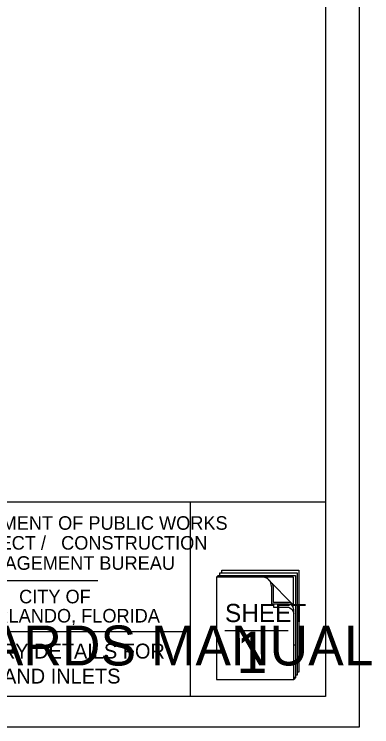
# Model space of a CAD drawing. Extents: x -7.1 to 10, y -5 to 6.
# Drawn here: x 7.28 to 10.04, y -5.04 to 0.46 of the extents above; entities that cross this region are included whole.
import ezdxf

# ---------------------------------------------------------------- set-up
doc = ezdxf.new("R2010")
doc.units = 0
doc.layers.add('Level 60', color=7, linetype='Continuous')
doc.layers.add('Level 62', color=7, linetype='Continuous')

msp = doc.modelspace()

# ---------------------------------------------------------------- linework, layer by layer
at = {"layer": 'Level 60'}
for p, q in [((9.2417, -3.9022), (9.4331, -4.0993)), ((7.9265, -3.9133), (7.1593, -3.9133)), ((9.416, -4.0867), (9.4347, -4.1006))]:
    msp.add_line(p, q, dxfattribs=at)
for points in [[(-7.0652, -5.0406), (9.9453, -5.0406), (9.9453, 5.9662), (-7.0652, 5.9662)], [(-6.384, 5.7493), (9.684, 5.7493), (9.684, -4.8063), (-6.384, -4.8063)], [(9.4356, -3.8861), (9.2545, -3.8861), (9.2077, -3.8863), (8.842, -3.8863), (8.8555, -3.8714), (9.4514, -3.8714), (9.4514, -4.6604), (9.4379, -4.6753), (9.4379, -4.1896), (9.4379, -4.1339), (9.4343, -4.1142), (9.4356, -4.0728)], [(8.842, -4.6753), (9.4379, -4.6753), (9.4379, -4.1896), (9.4379, -4.1589), (9.4379, -4.1339), (9.4379, -4.1339), (9.4343, -4.1142), (9.4227, -4.1021), (9.3973, -4.0928), (9.2703, -4.0928), (9.2703, -3.9645), (9.258, -3.919), (9.2361, -3.8965), (9.2077, -3.8863), (8.842, -3.8863)], [(9.2825, -4.0934), (9.2825, -4.1159), (9.3866, -4.1159), (9.3989, -4.1179), (9.4091, -4.122), (9.4189, -4.1288), (9.4269, -4.1368), (9.4314, -4.1454), (9.4379, -4.1658), (9.4377, -4.1327), (9.4343, -4.1142), (9.4227, -4.1021), (9.3973, -4.0928)]]:
    msp.add_lwpolyline(points, close=True, dxfattribs=at)
for points in [[(9.6844, -3.3069), (5.6643, -3.3069)], [(8.6415, -4.8065), (8.6415, -3.3069)], [(8.8826, -3.8528), (8.8826, -3.8305), (9.4785, -3.8305), (9.4785, -4.6195), (9.465, -4.6195)], [(8.8555, -3.8863), (8.8555, -3.8714), (9.4514, -3.8714), (9.4514, -4.6604), (9.4379, -4.6604)], [(8.8691, -3.8714), (8.8691, -3.8528), (9.465, -3.8528), (9.465, -4.6418), (9.4514, -4.6418)], [(9.416, -4.0867), (9.3995, -4.0807), (9.2825, -4.0807), (9.2825, -3.9626), (9.2739, -3.9354)], [(8.6415, -4.3066), (5.6643, -4.3066)], [(8.9073, -4.2967), (9.3946, -4.2967)], [(9.4536, -4.4113), (9.44, -4.4113)]]:
    msp.add_lwpolyline(points, dxfattribs=at)

# ---------------------------------------------------------------- texts
for s, height, p in [('DEPARTMENT OF PUBLIC WORKS', 0.104776, (6.6163, -3.5192)), ('PROJECT /   CONSTRUCTION', 0.104776, (6.7953, -3.6727)), ('MANAGEMENT BUREAU', 0.104773, (6.8954, -3.8284)), ('CITY OF', 0.10477, (7.3197, -4.0874)), ('SHEET', 0.14055, (8.9081, -4.2323)), ('ORLANDO, FLORIDA', 0.104773, (7.0278, -4.2355)), ('ENGINEERING STANDARDS MANUAL', 0.308157, (2.6812, -4.5672)), ('1 ', 0.31932, (8.9965, -4.6262))]:
    msp.add_text(s, height=height, dxfattribs=at).set_placement(p)
at = {"layer": 'Level 62'}
for s, p in [('SUPPLEMENTARY DETAILS FOR', (6.0333, -4.5137)), ('MANHOLES AND INLETS', (6.2895, -4.7069))]:
    msp.add_text(s, height=0.115042, dxfattribs=at).set_placement(p)

doc.saveas('drawing.dxf')
